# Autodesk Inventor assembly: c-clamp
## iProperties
Author: Elise Moss
Created: 2001-09
Part Number: c-clamp
Document SubType Name: Assembly
Designer: Elise Moss
Control State: 0
Master: False
Checked Out: False
PropertySet Name: Design Tracking Control
Length Units: 11272
Angle Units: 11279
Time Units: 11290
Mass Units: 11286
Shininess: 3
Angle Display Precision: 2
Document Length Units: 11272
Document Angle Units: 11286
Document Time Units: 11279
Document Mass Units: 11290
Document Length Units Precision: 3
Document Angle Units Precision: 2
Compacted: False
PropertySet Name: _Private Model Information
Density: 0.0
Volumn: 0.0
Area: 0.0
PropertySet Name: Model Information
